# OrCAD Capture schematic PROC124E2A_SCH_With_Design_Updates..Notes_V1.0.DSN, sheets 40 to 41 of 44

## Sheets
40 38. AUDIO CODEC: size C; title: AUDIO CODEC
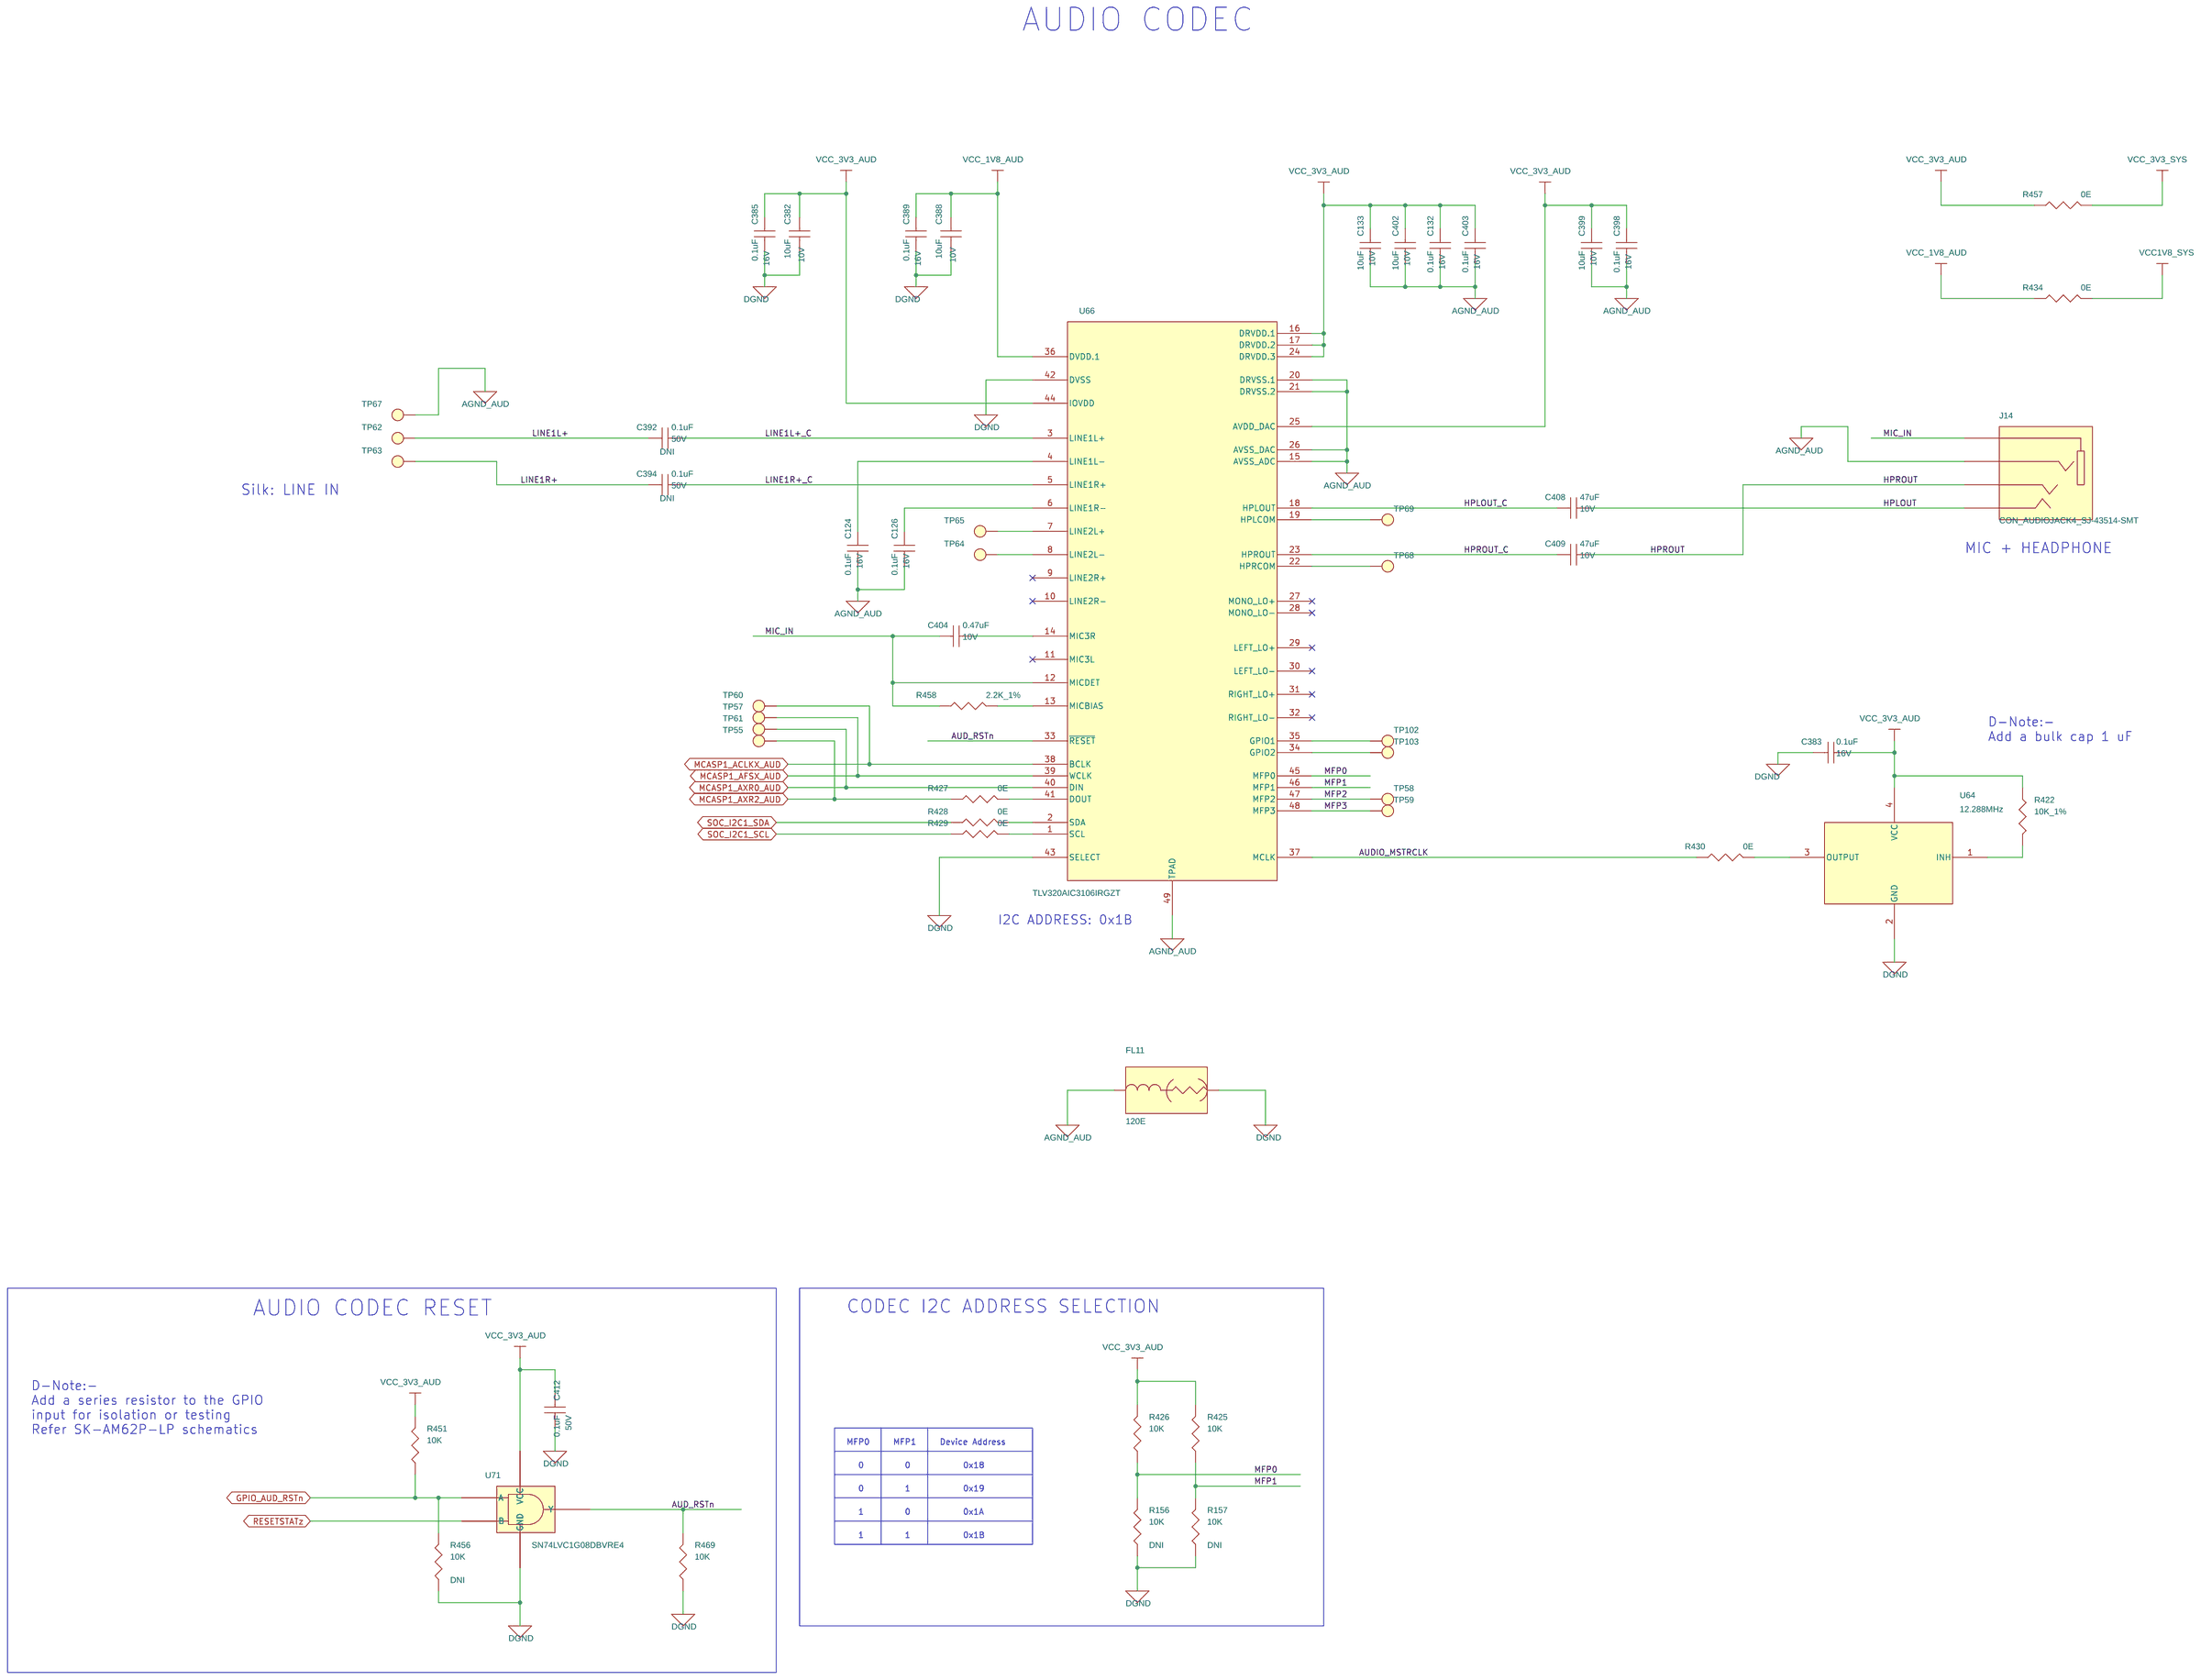
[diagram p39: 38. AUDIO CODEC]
41 40. HDMI INTERFACE: size C; title: HDMI INTERFACE
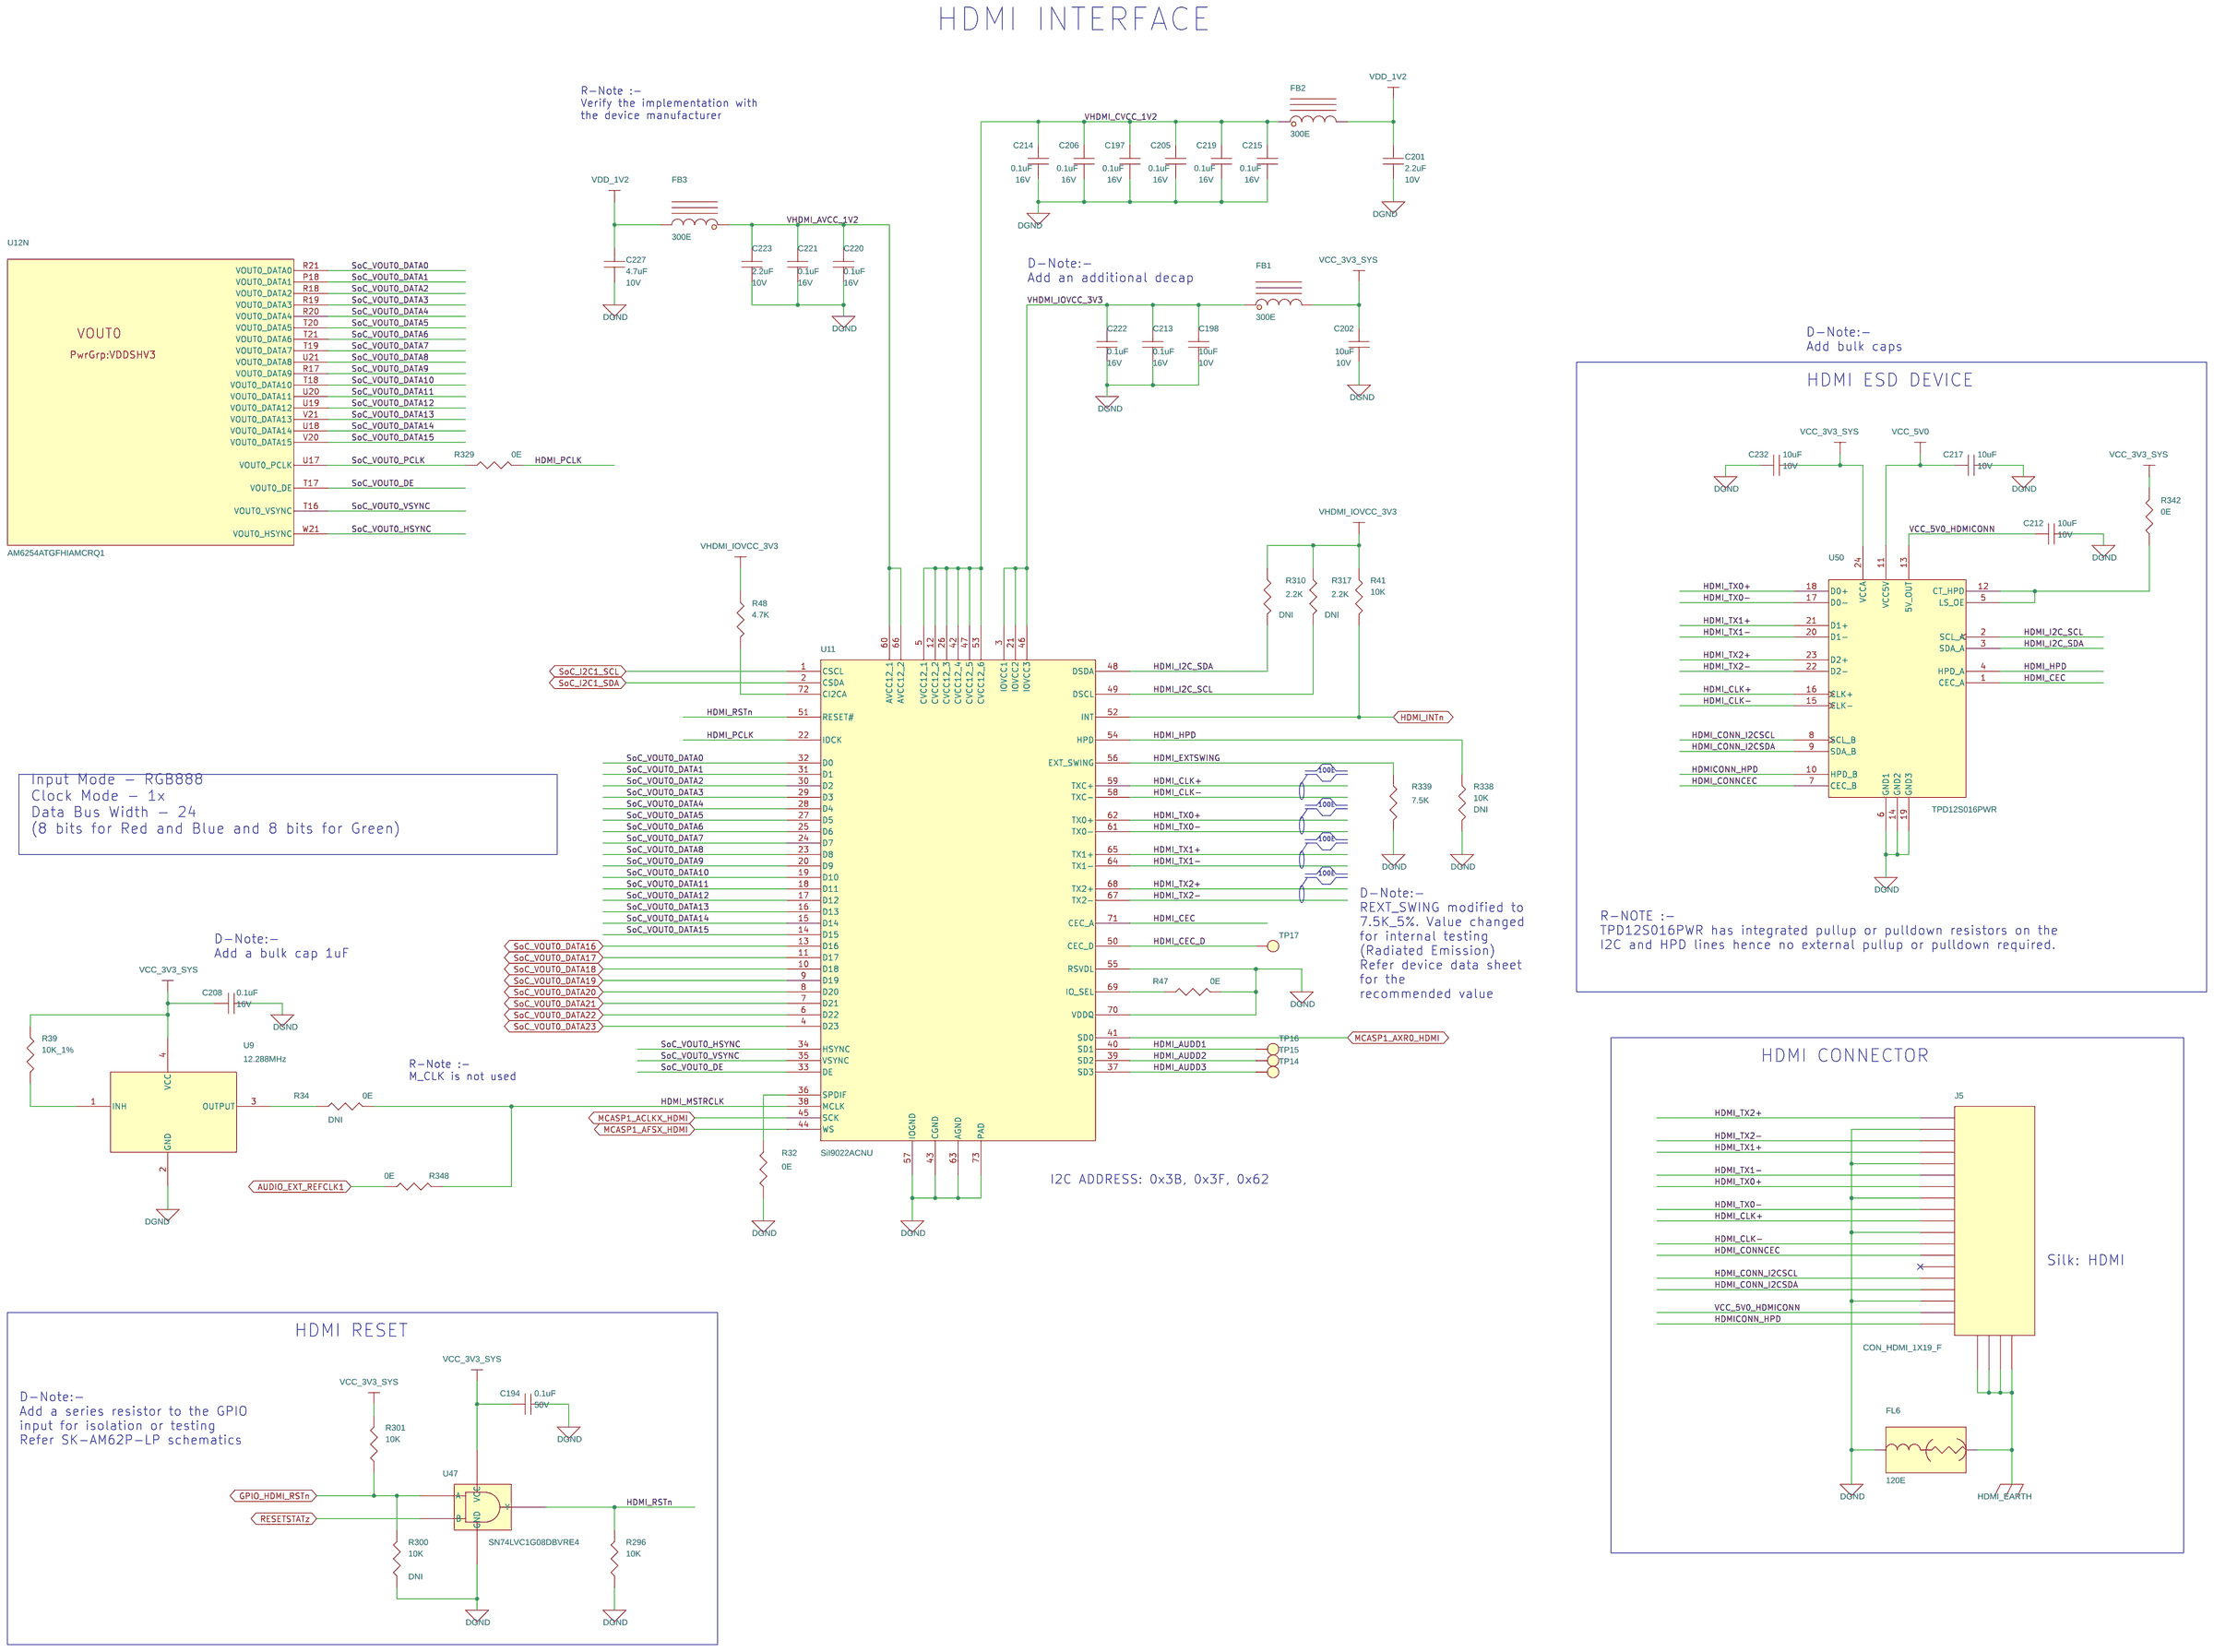
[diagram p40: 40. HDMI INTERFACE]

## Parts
sheet 15. SOC POWER CAPS
U12  AM6254ATGFHIAMCRQ1  [FCBGA441_31-49_680X680_2-6]  (sections A,B,C,D,E,F,G,H,I,J,K,L,M,N,O,P,Q,R)
sheet 38. AUDIO CODEC
C124  0.1uF  [CAP0201_0-5]
C126  0.1uF  [CAP0201_0-5]
C132  0.1uF  [CAP0201_0-5]
C133  10uF  [CAP0402_0-75]
C382  10uF  [CAP0402_0-75]
C383  0.1uF  [CAP0201_0-5]
C385  0.1uF  [CAP0201_0-5]
C388  10uF  [CAP0402_0-75]
C389  0.1uF  [CAP0201_0-5]
C392  0.1uF  [CAP0402_0-75]
C394  0.1uF  [CAP0402_0-75]
C398  0.1uF  [CAP0201_0-5]
C399  10uF  [CAP0402_0-75]
C402  10uF  [CAP0402_0-75]
C403  0.1uF  [CAP0201_0-5]
C404  0.47uF  [CAP0402_0-75]
C408  47uF  [CAP1206_2]
C409  47uF  [CAP1206_2]
C412  0.1uF  [CAP0402_0-75]
FL11  120E  [EMIFIL_BLM15A_0402_0-6]
J14  CON_AUDIOJACK4_SJ-43514-SMT  [CON_AV4_SJ-43514-SMT_S_R_S_5-1]
R156  10K  [RES0201_0-5]
R157  10K  [RES0201_0-5]
R422  10K_1%  [RES0201_0-5]
R425  10K  [RES0201_0-5]
R426  10K  [RES0201_0-5]
R427  0E  [RES0201_0-5]
R428  0E  [RES0201_0-5]
R429  0E  [RES0201_0-5]
R430  0E  [RES0201_0-5]
R434  0E  [RES0402_0-5]
R451  10K  [RES0201_0-5]
R456  10K  [RES0201_0-5]
R457  0E  [RES0402_0-5]
R458  2.2K_1%  [RES0201_0-5]
R469  10K  [RES0201_0-5]
TP55  TP20_SMD  [TP20_SMD]
TP57  TP20_SMD  [TP20_SMD]
TP58  TP20_SMD  [TP20_SMD]
TP59  TP20_SMD  [TP20_SMD]
TP60  TP20_SMD  [TP20_SMD]
TP61  TP20_SMD  [TP20_SMD]
TP62  THRU HOLE  [TP_40X65]
TP63  THRU HOLE  [TP_40X65]
TP64  TP20_SMD  [TP20_SMD]
TP65  TP20_SMD  [TP20_SMD]
TP67  THRU HOLE  [TP_40X65]
TP68  TP20_SMD  [TP20_SMD]
TP69  TP20_SMD  [TP20_SMD]
TP102  TP20_SMD  [TP20_SMD]
TP103  TP20_SMD  [TP20_SMD]
U64  12.288MHz  [OSC4_KC3225Z_130X100_SMD_0-8]
U66  TLV320AIC3106IRGZT  [VQFN48_19-68_285X285]
U71  SN74LVC1G08DBVRE4  [SOT23-5]
sheet 40. HDMI INTERFACE
C194  0.1uF  [CAP0402_0-75]
C197  0.1uF  [CAP0201_0-5]
C198  10uF  [CAP0402_0-75]
C201  2.2uF  [CAP0201_0-5]
C202  10uF  [CAP0402_0-75]
C205  0.1uF  [CAP0201_0-5]
C206  0.1uF  [CAP0201_0-5]
C208  0.1uF  [CAP0201_0-5]
C212  10uF  [CAP0402_0-75]
C213  0.1uF  [CAP0201_0-5]
C214  0.1uF  [CAP0201_0-5]
C215  0.1uF  [CAP0201_0-5]
C217  10uF  [CAP0402_0-75]
C219  0.1uF  [CAP0201_0-5]
C220  0.1uF  [CAP0201_0-5]
C221  0.1uF  [CAP0201_0-5]
C222  0.1uF  [CAP0201_0-5]
C223  2.2uF  [CAP0201_0-5]
C227  4.7uF  [CAP0402_0-75]
C232  10uF  [CAP0402_0-75]
FB1  300E  [IND0603]
FB2  300E  [IND0603]
FB3  300E  [IND0603]
FL6  120E  [EMIFIL_BLM15A_0402_0-6]
J5  CON_HDMI_1X19_F  [CON_19X1_10029449-001RLF_S_R_S_6-3]
R32  0E  [RES0201_0-5]
R34  0E  [RES0201_0-5]
R39  10K_1%  [RES0201_0-5]
R41  10K  [RES0201_0-5]
R47  0E  [RES0201_0-5]
R48  4.7K  [RES0201_0-5]
R296  10K  [RES0201_0-5]
R300  10K  [RES0201_0-5]
R301  10K  [RES0201_0-5]
R310  2.2K  [RES0402_0-5]
R317  2.2K  [RES0402_0-5]
R329  0E  [RES0201_0-5]
R338  10K  [RES0201_0-5]
R339  7.5K  [RES0402_0-5]
R342  0E  [RES0201_0-5]
R348  0E  [RES0201_0-5]
TP14  TP20_SMD  [TP20_SMD]
TP15  TP20_SMD  [TP20_SMD]
TP16  TP20_SMD  [TP20_SMD]
TP17  TP20_SMD  [TP20_SMD]
U9  12.288MHz  [OSC4_KC3225Z_130X100_SMD_0-8]
U11  SiI9022ACNU  [QFN72_19-68_390X390_0-9]
U47  SN74LVC1G08DBVRE4  [SOT23-5]
U50  TPD12S016PWR  [TSSOP24_25-59_315X180_1-2]

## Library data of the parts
U12 = AM6254ATGFHIAMCRQ1_FCBGA441: IC AM62Q SoC MICROPROCESSOR FCBGA441; Chkd/date: PRADEEP/180324; Crtd /date: TAMILARASU/180324; Custom_Duty: 15%; Customs_HS_Code: 85423100; Distributor_name: NA; Distributor_part_number: NA; Footprint Path: Y:\MIS_DATABASE\Library\ALTIUM_TOOL\PCB_FOOTPRINTS\Altium_Footprint_Lib.PcbLib; Height: 2.57MM; Library Path: Y:\MIS_DATABASE\Library\ALTIUM_TOOL\SCHEMATICS_PARTS\MS_MICROPROCESSOR_Library.schlib; Mfr_name: TEXAS INSTRUMENTS; Mistral Part No: 141224030001-R; Package: FCBGA441; Part_type: ICS\DIGITAL\MICROPROCESSOR; Project: TI_AM62Q_BRD; RoHS: NA; Temperature: NA; Tolerance: NA; Voltage: NA; Wattage: NA; Weight: NA; Datasheet: Y:\MIS_DATABASE\DATASHEETS\ICS\DIGITAL\MICROCONTROLLER\AM62Q-SoC.PDF
C124 C126 C132 C197 C205 C206 C213-C215 C219-C222 C383 C385 C389 C398 C403 = CAP: CAP CERAMIC 0.1uF 16V 10% X5R 0201; Chkd/date: MANIRAJA/230118; Crtd /date: MANIRAJA/230118; Custom_Duty: 15%; Customs_HS_Code: 85322990; Distributor_name: DIGIKEY; Distributor_part_number: 490-14305-1-ND; Footprint Path: Y:\MIS_DATABASE\Library\ALTIUM_TOOL\PCB_FOOTPRINTS\Altium_Footprint_Lib.PcbLib; Height: 0.33MM; Library Path: Y:\MIS_DATABASE\Library\ALTIUM_TOOL\SCHEMATICS_PARTS\MS_DISCRETE_Library.schlib; Mfr_name: MURATA; Mfr_part_number: GRM033R61C104KE14D; Mistral Part No: 120009030072-R; Package: 0201; Part_type: CAPACITORS\CERAMIC; Project: TI_MAXIE_CPB; RoHS: RoHS; Temperature: -55°C+85°C; Tolerance: 10%; Voltage: 16V; Wattage: NA; Weight: 0.33mg; Datasheet: Y:\MIS_DATABASE\DATASHEETS\CAPACITORS\GRM033R61C104KE14.PDF
C133 C198 C202 C212 C217 C232 C382 C388 C399 C402 = CAP: CAP CERAMIC 10uF 10V 20% X5R 0402; Chkd/date: MANIRAJA/300520; Crtd /date: ALVY/260520; Custom_Duty: 15%; Customs_HS_Code: 85322990; Distributor_name: DIGIKEY; Distributor_part_number: 490-GRM155R61A106ME11DTR-ND; Footprint Path: Y:\MIS_DATABASE\Library\ALTIUM_TOOL\PCB_FOOTPRINTS\Altium_Footprint_Lib.PcbLib; Height: 0.55MM; Library Path: Y:\MIS_DATABASE\Library\ALTIUM_TOOL\SCHEMATICS_PARTS\MS_DISCRETE_Library.schlib; Mfr_name: MURATA; Mfr_part_number: GRM155R61A106ME11D; Mistral Part No: 120013110019-R; Package: 0402; Part_type: CAPACITORS\CERAMIC; Project: QCS610_NANOSOM; RoHS: RoHS; Temperature: -55°C+85°C; Tolerance: 20%; Voltage: 10V; Wattage: NA; Weight: 3.1mg; Datasheet: Y:\MIS_DATABASE\DATASHEETS\CAPACITORS\MURATA-GXX-SER_NOV17.PDF
C392 C394 = CAP: CAP CERAMIC 0.1uF 50V 10% X7R 0402; Assembly_Instruction: DNI; Chkd/date: MANIRAJA/261020; Crtd /date: ALVY/211020; Custom_Duty: 15%; Customs_HS_Code: 85322990; Distributor_name: DIGIKEY; Distributor_part_number: 490-10700-1-ND; Footprint Path: Y:\MIS_DATABASE\Library\ALTIUM_TOOL\PCB_FOOTPRINTS\Altium_Footprint_Lib.PcbLib; Height: 0.55MM; Library Path: Y:\MIS_DATABASE\Library\ALTIUM_TOOL\SCHEMATICS_PARTS\MS_DISCRETE_Library.schlib; Mfr_name: MURATA; Mfr_part_number: GRM155R71H104KE14D; Mistral Part No: 120011100014-R; Package: 0402; Part_type: CAPACITORS\CERAMIC; Project: J7_CP; RoHS: RoHS; Temperature: -55°C+125°C; Tolerance: 10%; Voltage: 50V; Wattage: NA; Weight: 3.1mg; Datasheet: Y:\MIS_DATABASE\DATASHEETS\CAPACITORS\GRM155R71H104KE14.PDF
C404 = CAP: CAP CERAMIC 0.47uF 10V 10% X7R 0402; Chkd/date: MANIRAJA/310821; Crtd /date: ALVY/310821; Custom_Duty: 15%; Customs_HS_Code: 85322990; Distributor_name: DIGIKEY; Distributor_part_number: 490-14366-1-ND; Footprint Path: Y:\MIS_DATABASE\Library\ALTIUM_TOOL\PCB_FOOTPRINTS\Altium_Footprint_Lib.PcbLib; Height: 0.55MM; Library Path: Y:\MIS_DATABASE\Library\ALTIUM_TOOL\SCHEMATICS_PARTS\MS_DISCRETE_Library.schlib; Mfr_name: MURATA; Mfr_part_number: GRM155R71A474KE01D; Mistral Part No: 120021060019-R; Package: 0402; Part_type: CAPACITORS\CERAMIC; Project: TI_AM335x SK_BRD; RoHS: RoHS; Temperature: -55°C+125°C; Tolerance: 10%; Voltage: 10V; Wattage: NA; Weight: 1.5mg; Datasheet: Y:\MIS_DATABASE\DATASHEETS\CAPACITORS\GRM155R71A474KE01.PDF
C408 C409 = CAP: CAP CERAMIC 47uF 10V 20% X5R 1206; Chkd/date: USMAN/121213; Crtd /date: USMAN/121213; Custom_Duty: 15%; Customs_HS_Code: 85322990; Distributor_name: DIGIKEY; Distributor_part_number: 490-5528-1-ND; Footprint Path: Y:\MIS_DATABASE\Library\ALTIUM_TOOL\PCB_FOOTPRINTS\Altium_Footprint_Lib.PcbLib; Height: 1.80MM; Library Path: Y:\MIS_DATABASE\Library\ALTIUM_TOOL\SCHEMATICS_PARTS\MS_DISCRETE_Library.schlib; Mfr_name: MURATA; Mfr_part_number: GRM31CR61A476ME15L; Mistral Part No: 120013120015-R; Package: 1206; Part_type: CAPACITORS\CERAMIC; Project: DMP; RoHS: RoHS; Temperature: -55°C+85°C; Tolerance: 20%; Voltage: 10V; Wattage: NA; Weight: 40mg; Datasheet: Y:\MIS_DATABASE\DATASHEETS\CAPACITORS\MURATA-GXX-SER_NOV17.PDF
C412 = CAP: CAP CERAMIC 0.1uF 50V 10% X7R 0402; Chkd/date: MANIRAJA/261020; Crtd /date: ALVY/211020; Custom_Duty: 15%; Customs_HS_Code: 85322990; Distributor_name: DIGIKEY; Distributor_part_number: 490-10700-1-ND; Footprint Path: Y:\MIS_DATABASE\Library\ALTIUM_TOOL\PCB_FOOTPRINTS\Altium_Footprint_Lib.PcbLib; Height: 0.55MM; Library Path: Y:\MIS_DATABASE\Library\ALTIUM_TOOL\SCHEMATICS_PARTS\MS_DISCRETE_Library.schlib; Mfr_name: MURATA; Mfr_part_number: GRM155R71H104KE14D; Mistral Part No: 120011100014-R; Package: 0402; Part_type: CAPACITORS\CERAMIC; Project: J7_CP; RoHS: RoHS; Temperature: -55°C+125°C; Tolerance: 10%; Voltage: 50V; Wattage: NA; Weight: 3.1mg; Datasheet: Y:\MIS_DATABASE\DATASHEETS\CAPACITORS\GRM155R71H104KE14.PDF
FL6 FL11 = EMIFILTER_IND: IND FERRITE BEAD CHIP 120E 2A 0402; Chkd/date: NAVEED/241114; Crtd /date: USMAN/170613; Custom_Duty: 24%; Customs_HS_Code: 85369090; Distributor_name: DIGIKEY; Distributor_part_number: 490-9656-1-ND; Footprint Path: Y:\MIS_DATABASE\Library\ALTIUM_TOOL\PCB_FOOTPRINTS\Altium_Footprint_Lib.PcbLib; Height: 0.55MM; Library Path: Y:\MIS_DATABASE\Library\ALTIUM_TOOL\SCHEMATICS_PARTS\MS_FILTER_Library.schlib; Mfr_name: MURATA; Mfr_part_number: BLM15PX121SN1D; Mistral Part No: 130013060022-R; Package: 0402; Part_type: INDUCTOR; Project: GEN_3-8; RoHS: RoHS; Temperature: -55°C+125°C; Tolerance: 25%; Voltage: NA; Wattage: NA; Weight: 1mg; Datasheet: Y:\MIS_DATABASE\DATASHEETS\DISCRETES\INDUCTORS\BLM15-SN1-SER.PDF
J14 = CON_AUDIOJACK4_SJ-43514-SMT: CON AUDIO JACK 4POS FEMALE RT SMD; Chkd/date: MAZHAR/230211; Crtd /date: MUDDU/300610; Custom_Duty: 24%; Customs_HS_Code: 85369090; Distributor_name: DIGIKEY; Distributor_part_number: CP-43514SJCT-ND; Footprint Path: Y:\MIS_DATABASE\Library\ALTIUM_TOOL\PCB_FOOTPRINTS\Altium_Footprint_Lib.PcbLib; Height: 5.10MM; Library Path: Y:\MIS_DATABASE\Library\ALTIUM_TOOL\SCHEMATICS_PARTS\MS_CONNECTOR_Library.schlib; Mfr_name: CUI INC; Mfr_part_number: SJ-43514-SMT-TR; Mistral Part No: 150010060028-R; Package: SMD; Part_type: CONNECTOR\JACK; Project: PB_BUGBASE; RoHS: RoHS; Temperature: -25°C+85°C; Tolerance: NA; Voltage: NA; Wattage: NA; Weight: 1100mg; Datasheet: Y:\MIS_DATABASE\DATASHEETS\CONNECTORS\SJ-4351X-SMT.PDF
R156 R157 R300 R338 R456 = RESISTOR: RES 10K 1/20W 5% 0201; Assembly_Instruction: DNI; Chkd/date: MANIRAJA/050517; Crtd /date: MANIRAJA/050517; Custom_Duty: 15%; Customs_HS_Code: 85332119; Distributor_name: DIGIKEY; Distributor_part_number: 311-10KNCT-ND; Footprint Path: Y:\MIS_DATABASE\Library\ALTIUM_TOOL\PCB_FOOTPRINTS\Altium_Footprint_Lib.PcbLib; Height: 0.26MM; Library Path: Y:\MIS_DATABASE\Library\ALTIUM_TOOL\SCHEMATICS_PARTS\MS_DISCRETE_Library.schlib; Mfr_name: YAGEO AMERICA; Mfr_part_number: RC0201JR-0710KL; Mistral Part No: 110010070051-R; Package: 0201; Part_type: RESISTORS\FIXED; Project: GOLDEN-I LITE; RoHS: RoHS; Temperature: -55°C+125°C; Tolerance: 5%; Voltage: NA; Wattage: 1/20W; Weight: 0.17mg; Datasheet: Y:\MIS_DATABASE\DATASHEETS\RESISTORS\RCXXXXL-SER_MAR18.PDF
R39 R422 = RESISTOR: RES 10K 1/20W 1% 0201; Chkd/date: VASANTHA/270117; Crtd /date: MANIRAJA/270117; Custom_Duty: 15%; Customs_HS_Code: 85332119; Distributor_name: DIGIKEY; Distributor_part_number: 311-10.0KMCT-ND; Footprint Path: Y:\MIS_DATABASE\Library\ALTIUM_TOOL\PCB_FOOTPRINTS\Altium_Footprint_Lib.PcbLib; Height: 0.26MM; Library Path: Y:\MIS_DATABASE\Library\ALTIUM_TOOL\SCHEMATICS_PARTS\MS_DISCRETE_Library.schlib; Mfr_name: YAGEO AMERICA; Mfr_part_number: RC0201FR-0710KL; Mistral Part No: 110011040018-R; Package: 0201; Part_type: RESISTORS\FIXED; Project: GOLDEN-I LITE; RoHS: RoHS; Temperature: -55°C+125°C; Tolerance: 1%; Voltage: NA; Wattage: 1/20W; Weight: 0.17mg; Datasheet: Y:\MIS_DATABASE\DATASHEETS\RESISTORS\RCXXXXL-SER_MAR18.PDF
R41 R296 R301 R425 R426 R451 R469 = RESISTOR: RES 10K 1/20W 5% 0201; Chkd/date: MANIRAJA/050517; Crtd /date: MANIRAJA/050517; Custom_Duty: 15%; Customs_HS_Code: 85332119; Distributor_name: DIGIKEY; Distributor_part_number: 311-10KNCT-ND; Footprint Path: Y:\MIS_DATABASE\Library\ALTIUM_TOOL\PCB_FOOTPRINTS\Altium_Footprint_Lib.PcbLib; Height: 0.26MM; Library Path: Y:\MIS_DATABASE\Library\ALTIUM_TOOL\SCHEMATICS_PARTS\MS_DISCRETE_Library.schlib; Mfr_name: YAGEO AMERICA; Mfr_part_number: RC0201JR-0710KL; Mistral Part No: 110010070051-R; Package: 0201; Part_type: RESISTORS\FIXED; Project: GOLDEN-I LITE; RoHS: RoHS; Temperature: -55°C+125°C; Tolerance: 5%; Voltage: NA; Wattage: 1/20W; Weight: 0.17mg; Datasheet: Y:\MIS_DATABASE\DATASHEETS\RESISTORS\RCXXXXL-SER_MAR18.PDF
R32 R47 R342 R348 R427-R430 = RESISTOR: RES 0E 1/20W 5% 0201; Chkd/date: NAVEED/301214; Crtd /date: MUDDU/120710; Custom_Duty: 15%; Customs_HS_Code: 85332119; Distributor_name: DIGIKEY; Distributor_part_number: 311-0.0NCT-ND; Footprint Path: Y:\MIS_DATABASE\Library\ALTIUM_TOOL\PCB_FOOTPRINTS\Altium_Footprint_Lib.PcbLib; Height: 0.26MM; Library Path: Y:\MIS_DATABASE\Library\ALTIUM_TOOL\SCHEMATICS_PARTS\MS_DISCRETE_Library.schlib; Mfr_name: YAGEO AMERICA; Mfr_part_number: RC0201JR-070RL; Mistral Part No: 110010070067-R; Package: 0201; Part_type: RESISTORS\FIXED; Project: PB_BUGBASE; RoHS: RoHS; Temperature: -55°C+125°C; Tolerance: 5%; Voltage: NA; Wattage: 1/20W; Weight: 0.17mg; Datasheet: Y:\MIS_DATABASE\DATASHEETS\RESISTORS\RCXXXXL-SER_MAR18.PDF
R434 R457 = RESISTOR: RES 0E 1/16W JUMPER 0402; Chkd/date: VASANTHA/201216; Crtd /date: MUDDU/190810; Custom_Duty: 15%; Customs_HS_Code: 85332119; Distributor_name: DIGIKEY; Distributor_part_number: 541-0.0JCT-ND; Footprint Path: Y:\MIS_DATABASE\Library\ALTIUM_TOOL\PCB_FOOTPRINTS\Altium_Footprint_Lib.PcbLib; Height: 0.40MM; Library Path: Y:\MIS_DATABASE\Library\ALTIUM_TOOL\SCHEMATICS_PARTS\MS_DISCRETE_Library.schlib; Mfr_name: VISHAY; Mfr_part_number: CRCW04020000Z0ED; Mistral Part No: 110010080019-R; Package: 0402; Part_type: RESISTORS\FIXED; Project: PB_BUGBASE; RoHS: RoHS; Temperature: -55°C+155°C; Tolerance: NA; Voltage: NA; Wattage: 1/16W; Weight: 0.65mg; Datasheet: Y:\MIS_DATABASE\DATASHEETS\RESISTORS\CRCW0603.PDF
R458 = RESISTOR: RES 2.2K 1/20W 1% 0201; Chkd/date: VASANTHA/270117; Crtd /date: MANIRAJA/270117; Custom_Duty: 15%; Customs_HS_Code: 85332119; Distributor_name: DIGIKEY; Distributor_part_number: YAG2572CT-ND; Footprint Path: Y:\MIS_DATABASE\Library\ALTIUM_TOOL\PCB_FOOTPRINTS\Altium_Footprint_Lib.PcbLib; Height: 0.26MM; Library Path: Y:\MIS_DATABASE\Library\ALTIUM_TOOL\SCHEMATICS_PARTS\MS_DISCRETE_Library.schlib; Mfr_name: YAGEO AMERICA; Mfr_part_number: RC0201FR-072K2L; Mistral Part No: 110017010016-R; Package: 0201; Part_type: RESISTORS\FIXED; Project: GOLDEN-I LITE; RoHS: RoHS; Temperature: -55°C+125°C; Tolerance: 1%; Voltage: NA; Wattage: 1/20W; Weight: 0.17mg; Datasheet: Y:\MIS_DATABASE\DATASHEETS\RESISTORS\RCXXXXL-SER_MAR18.PDF
TP14-TP17 TP55 TP57-TP61 TP64 TP65 TP68 TP69 TP102 TP103 = TESTPOINT: TESTPOINT CIR 20 SMD; Chkd/date: SHREESHAIL/171006; Crtd /date: MAZHAR/171006; Custom_Duty: NA; Customs_HS_Code: NA; Distributor_name: NA; Distributor_part_number: NA; Footprint Path: Y:\MIS_DATABASE\Library\ALTIUM_TOOL\PCB_FOOTPRINTS\Altium_Footprint_Lib.PcbLib; Height: NA; Library Path: Y:\MIS_DATABASE\Library\ALTIUM_TOOL\SCHEMATICS_PARTS\MS_DISCRETE_Library.schlib; MECHANICAL 3D STEP FILE: NA; Mfr_name: LOCAL; Mistral Part No: NA; Package: SMD; Project: BT MODULE_CSRBC04; RoHS: NA; Temperature: NA; Tolerance: NA; Voltage: NA; Wattage: NA; Weight: NA; Datasheet: NA
TP62 TP63 TP67 = TESTPOINT: TESTPOINT 1.0MM DRILL PTH; Chkd/date: MAZHAR/271211; Crtd /date: SHREESHAIL/041005; Distributor_name: NA; Distributor_part_number: NA; Height: NA; Mfr_name: LOCAL; Mistral Part No: 130009030938; Package: THRU-HOLE; Project: HSE; Datasheet: NA
U9 U64 = OSC_KC2016K: OSC 12.288MHz CMOS SMD; Chkd/date: ALVY/240322; Crtd /date: ALVY/240322; Custom_Duty: 24%; Customs_HS_Code: 85437099; Distributor_name: DIGIKEY; Distributor_part_number: 478-KC3225Z12.2880C1KX00CT-ND; Footprint Path: Y:\MIS_DATABASE\Library\ALTIUM_TOOL\PCB_FOOTPRINTS\Altium_Footprint_Lib.PcbLib; Height: 0.80MM; Library Path: Y:\MIS_DATABASE\Library\ALTIUM_TOOL\SCHEMATICS_PARTS\MS_DISCRETE_Library.schlib; Mfr_name: KYOCERA; Mfr_part_number: KC3225Z12.2880C1KX00; Mistral Part No: 130022030052-R; Package: SMD; Part_type: OSCILLATORS; Project: TI_SK-AM62Q-LP EVM_BRD; RoHS: RoHS; Temperature: -40°C+85°C; Tolerance: NA; Voltage: NA; Wattage: NA; Weight: NA; Datasheet: Y:\MIS_DATABASE\DATASHEETS\MISC\CRY_OSC\KC-Z-SERPDF
U66 = TLV320AIC3106IRGZT_VQFN48: IC LOW-POWER STEREO AUDIO CODEC VQFN48; Chkd/date: SUHAS/261010; Crtd /date: MUDDU/150610; Custom_Duty: 15%; Customs_HS_Code: 85423100; Distributor_name: DIGIKEY; Distributor_part_number: TLV320AIC3106IRGZT-ND; Height: 1.00MM; Mfr_name: TEXAS INSTRUMENTS; Mistral Part No: 143010060003-R; Package: VQFN48; Part_type: ICS\TELECOM\CODEC; Project: CENTAURUS; RoHS: Sb/ Br FREE; Temperature: -40°C+85°C; Weight: NA; Datasheet: Y:\MIS_DATABASE\DATASHEETS\ICS\TELECOM\TLV320AIC3106IRGZT.PDF
U47 U71 = SN74LVC1G08DBVRE4_SOT23-5: IC SINGLE 2-INPUT POSITIVE AND GATE SOT23-5; Chkd/date: SUHAS/221010; Crtd /date: USMAN/151008; Custom_Duty: 15%; Customs_HS_Code: 85423100; Distributor_name: DIGIKEY; Distributor_part_number: SN74LVC1G08DBVRE4-ND; Height: 1.45MM; Mfr_name: TEXAS INSTRUMENTS; Mistral Part No: 141009060026-R; Part_type: ICS\DIGITAL\GATES; Project: KHAN_MAIN; RoHS: Sb/ Br FREE; Temperature: -40°C+85°C; Datasheet: Y:\MIS_DATABASE\DATASHEETS\ICS\DIGITAL\GATES\SN74LVC1G08.PDF
C194 = CAP: CAP CERAMIC 0.1uF 50V 10% X7R 0402; Alt_Mfr_name: YAGEO AMERICA; Alt_Mfr_part_number: CC0402KRX5R8BB104; Chkd/date: MANIRAJA/261020; Crtd /date: ALVY/211020; Custom_Duty: 15%; Customs_HS_Code: 85322990; Distributor_name: DIGIKEY; Distributor_part_number: 490-10700-1-ND; Footprint Path: Y:\MIS_DATABASE\Library\ALTIUM_TOOL\PCB_FOOTPRINTS\Altium_Footprint_Lib.PcbLib; Height: 0.55MM; Library Path: Y:\MIS_DATABASE\Library\ALTIUM_TOOL\SCHEMATICS_PARTS\MS_DISCRETE_Library.schlib; Mfr_name: MURATA; Mfr_part_number: GRM155R71H104KE14D; Mistral Part No: 120011100014-R; Package: 0402; Part_type: CAPACITORS\CERAMIC; Project: J7_CP; RoHS: RoHS; Temperature: -55°C+125°C; Tolerance: 10%; Voltage: 50V; Wattage: NA; Weight: 3.1mg; Datasheet: Y:\MIS_DATABASE\DATASHEETS\CAPACITORS\GRM155R71H104KE14.PDF
C201 C223 = CAP: CAP CERAMIC 2.2uF 10V 10% X5R 0201; Chkd/date: MANIRAJA/220918; Crtd /date: MANIRAJA/220918; Custom_Duty: 15%; Customs_HS_Code: 85322990; Distributor_name: DIGIKEY; Distributor_part_number: 490-13227-1-ND; Footprint Path: Y:\MIS_DATABASE\Library\ALTIUM_TOOL\PCB_FOOTPRINTS\Altium_Footprint_Lib.PcbLib; Height: 0.39MM; Library Path: Y:\MIS_DATABASE\Library\ALTIUM_TOOL\SCHEMATICS_PARTS\MS_DISCRETE_Library.schlib; Mfr_name: MURATA; Mfr_part_number: GRM033R61A225KE47D; Mistral Part No: 120018090044-R; Package: 0201; Part_type: CAPACITORS\CERAMIC; Project: TI_60GHz-AOP; RoHS: RoHS; Temperature: -55°C+85°C; Tolerance: 10%; Voltage: 10V; Wattage: NA; Weight: 0.33mg; Datasheet: Y:\MIS_DATABASE\DATASHEETS\CAPACITORS\GRM033R61A225KE47D.PDF
C208 = CAP: CAP CERAMIC 0.1uF 16V 10% X5R 0201; Alt_Mfr_name: YAGEO AMERICA; Alt_Mfr_part_number: CC0402KRX5R8BB104; Chkd/date: MANIRAJA/230118; Crtd /date: MANIRAJA/230118; Custom_Duty: 15%; Customs_HS_Code: 85322990; Distributor_name: DIGIKEY; Distributor_part_number: 490-14305-1-ND; Footprint Path: Y:\MIS_DATABASE\Library\ALTIUM_TOOL\PCB_FOOTPRINTS\Altium_Footprint_Lib.PcbLib; Height: 0.33MM; Library Path: Y:\MIS_DATABASE\Library\ALTIUM_TOOL\SCHEMATICS_PARTS\MS_DISCRETE_Library.schlib; Mfr_name: MURATA; Mfr_part_number: GRM033R61C104KE14D; Mistral Part No: 120009030072-R; Package: 0201; Part_type: CAPACITORS\CERAMIC; Project: TI_MAXIE_CPB; RoHS: RoHS; Temperature: -55°C+85°C; Tolerance: 10%; Voltage: 16V; Wattage: NA; Weight: 0.33mg; Datasheet: Y:\MIS_DATABASE\DATASHEETS\CAPACITORS\GRM033R61C104KE14.PDF
C227 = CAP: CAP CERAMIC 4.7uF 10V 20% X5R 0402; Chkd/date: MANIRAJA/110718; Crtd /date: ALVY/110718; Custom_Duty: 15%; Customs_HS_Code: 85322990; Distributor_name: DIGIKEY; Distributor_part_number: 490-14306-1-ND; Footprint Path: Y:\MIS_DATABASE\Library\ALTIUM_TOOL\PCB_FOOTPRINTS\Altium_Footprint_Lib.PcbLib; Height: 0.65MM; Library Path: Y:\MIS_DATABASE\Library\ALTIUM_TOOL\SCHEMATICS_PARTS\MS_DISCRETE_Library.schlib; Mfr_name: MURATA; Mfr_part_number: GRM155R61A475MEAAD; Mistral Part No: 120012060002-R; Package: 0402; Part_type: CAPACITORS\CERAMIC; Project: TI_J7SVB_PCIE_ADD-ON-CARD; RoHS: RoHS; Temperature: -55°C+85°C; Tolerance: 20%; Voltage: 10V; Wattage: NA; Weight: 14mg; Datasheet: Y:\MIS_DATABASE\DATASHEETS\CAPACITORS\GRM155R61A475MEAAD.PDF
FB1-FB3 = INDUCTOR_FERRITE: IND FERRITE CHIP 300E 500mA 0603; Alternate_mfr_name_A: TDK CORPORATION; Alternate_mfr_part_number_A: MMZ1608R301ATA00; Chkd/date: VASANTHA/190614; Crtd /date: NAVEED/160614; Custom_Duty: 24%; Customs_HS_Code: 85437099; Distributor_name: DIGIKEY; Distributor_name_A: DIGIKEY; Distributor_part_number: 445-2171-1-ND; Distributor_part_number_A: 445-2171-1-ND; Height: 0.75MM; Mfr_name: TDK CORPORATION; Mfr_part_number: MMZ1608R301A; Mistral Part No: 130014060028-R; Package: 0603; Part_type: INDUCTOR; Project: AEGIS_POM; RoHS: RoHS; Temperature: -55°C+125°C; Tolerance: NA; Voltage: NA; Wattage: NA; Weight: NA; Datasheet: Y:\MIS_DATABASE\DATASHEETS\DISCRETES\INDUCTORS\MMZSER.PDF
J5 = CON_HDMI_19X1: CON HDMI-A TYPE 1X19 0.50MM PITCH FEMALE RT SMD; Chkd/date: VASANTHA/060117; Crtd /date: MUDDU/060510; Custom_Duty: 24%; Customs_HS_Code: 85369090; Distributor_name: DIGIKEY; Distributor_part_number: 609-1010-1-ND; Footprint Path: Y:\MIS_DATABASE\Library\ALTIUM_TOOL\PCB_FOOTPRINTS\Altium_Footprint_Lib.PcbLib; Height: 6.30MM; Library Path: Y:\MIS_DATABASE\Library\ALTIUM_TOOL\SCHEMATICS_PARTS\MS_CONNECTOR_Library.schlib; Mfr_name: FCI; Mfr_part_number: 10029449-001RLF; Mistral Part No: 150010050001-R; Package: SMD; Part_type: CONNECTOR\HDMI; Project: SHIVA; RoHS: RoHS; Temperature: -20°C+85°C; Tolerance: NA; Voltage: NA; Wattage: NA; Weight: 2700mg; Datasheet: Y:\MIS_DATABASE\DATASHEETS\CONNECTORS\10029449-001RLF.PDF
R34 = RESISTOR: RES 0E 1/20W 5% 0201; Assembly_Instruction: DNI; Chkd/date: NAVEED/301214; Crtd /date: MUDDU/120710; Custom_Duty: 15%; Customs_HS_Code: 85332119; Distributor_name: DIGIKEY; Distributor_part_number: 311-0.0NCT-ND; Footprint Path: Y:\MIS_DATABASE\Library\ALTIUM_TOOL\PCB_FOOTPRINTS\Altium_Footprint_Lib.PcbLib; Height: 0.26MM; Library Path: Y:\MIS_DATABASE\Library\ALTIUM_TOOL\SCHEMATICS_PARTS\MS_DISCRETE_Library.schlib; Mfr_name: YAGEO AMERICA; Mfr_part_number: RC0201JR-070RL; Mistral Part No: 110010070067-R; Package: 0201; Part_type: RESISTORS\FIXED; Project: PB_BUGBASE; RoHS: RoHS; Temperature: -55°C+125°C; Tolerance: 5%; Voltage: NA; Wattage: 1/20W; Weight: 0.17mg; Datasheet: Y:\MIS_DATABASE\DATASHEETS\RESISTORS\RCXXXXL-SER_MAR18.PDF
R48 = RESISTOR: RES 4.7K 1/20W 5% 0201; Chkd/date: MANIRAJA/200921; Crtd /date: ALVY/200921; Custom_Duty: 15%; Customs_HS_Code: 85332119; Distributor_name: DIGIKEY; Distributor_part_number: 311-4.7KNCT-ND; Footprint Path: Y:\MIS_DATABASE\Library\ALTIUM_TOOL\PCB_FOOTPRINTS\Altium_Footprint_Lib.PcbLib; Height: 0.26MM; Library Path: Y:\MIS_DATABASE\Library\ALTIUM_TOOL\SCHEMATICS_PARTS\MS_DISCRETE_Library.schlib; Mfr_name: YAGEO AMERICA; Mfr_part_number: RC0201JR-074K7L; Mistral Part No: 110021090007-R; Package: 0201; Part_type: RESISTORS\FIXED; Project: TI_AM62x SKEVM_BRD; RoHS: RoHS; Temperature: -55°C+125°C; Tolerance: 5%; Voltage: NA; Wattage: 1/20W; Weight: 0.17mg; Datasheet: Y:\MIS_DATABASE\DATASHEETS\RESISTORS\RCXXXXL-SER_MAR18.PDF
R310 R317 = RESISTOR: RES 2.2K 1/16W 5% 0402; Assembly_Instruction: DNI; Chkd/date: VASANTHA/061216; Crtd /date: BAVISH/021210; Custom_Duty: 15%; Customs_HS_Code: 85332119; Distributor_name: DIGIKEY; Distributor_part_number: 311-2.2KJRCT-ND; Footprint Path: Y:\MIS_DATABASE\Library\ALTIUM_TOOL\PCB_FOOTPRINTS\Altium_Footprint_Lib.PcbLib; Height: 0.40MM; Library Path: Y:\MIS_DATABASE\Library\ALTIUM_TOOL\SCHEMATICS_PARTS\MS_DISCRETE_Library.schlib; Mfr_name: YAGEO AMERICA; Mfr_part_number: RC0402JR-072K2L; Mistral Part No: 110010120018-R; Package: 0402; Part_type: RESISTORS\FIXED; Project: TE4; RoHS: RoHS; Temperature: -55°C+155°C; Tolerance: 5%; Voltage: NA; Wattage: 1/16W; Weight: 0.65mg; Datasheet: Y:\MIS_DATABASE\DATASHEETS\RESISTORS\RCXXXXL-SER_MAR18.PDF
R329 = RESISTOR: RES 0E 1/20W 5% 0201; Chkd/date: NAVEED/301214; Crtd /date: MUDDU/120710; Custom_Duty: 15%; Customs_HS_Code: 85332119; Distributor_name: DIGIKEY; Distributor_part_number: 311-0.0NCT-ND; Footprint Path: Y:\MIS_DATABASE\Library\ALTIUM_TOOL\PCB_FOOTPRINTS\Altium_Footprint_Lib.PcbLib; Height: 0.26MM; Library Path: Y:\MIS_DATABASE\Library\ALTIUM_TOOL\SCHEMATICS_PARTS\MS_DISCRETE_Library.schlib; Mfr_name: YAGEO AMERICA; Mfr_part_number: RC0201JR-070RL; Mistral Part No: 110010070067-R; Package: 0201; Part_type: RESISTORS\FIXED; Project: PB_BUGBASE; RoHS: RoHS; SIGNAL_MODEL: RESISTOR_RES0201_0-5_0E_0E; Temperature: -55°C+125°C; Tolerance: 5%; Voltage: NA; Wattage: 1/20W; Weight: 0.17mg; Datasheet: Y:\MIS_DATABASE\DATASHEETS\RESISTORS\RCXXXXL-SER_MAR18.PDF
R339 = RESISTOR: RES 7.5K 1/16W 5% 0402; Chkd/date: MAZHAR/280108; Crtd /date: USMAN/280108; Custom_Duty: 15%; Customs_HS_Code: 85332119; Distributor_name: DIGIKEY; Distributor_part_number: 541-7.5KJCT-ND; Footprint Path: Y:\MIS_DATABASE\Library\ALTIUM_TOOL\PCB_FOOTPRINTS\Altium_Footprint_Lib.PcbLib; Height: 0.40MM; Library Path: Y:\MIS_DATABASE\Library\ALTIUM_TOOL\SCHEMATICS_PARTS\MS_DISCRETE_Library.schlib; Mfr_name: VISHAY; Mfr_part_number: CRCW04027K50JNED; Mistral Part No: 110009031092-R; Package: 0402; Part_type: RESISTORS\FIXED; Project: TELEMETRY ENCODER; RoHS: RoHS; Temperature: -55°C+155°C; Tolerance: 5%; Voltage: NA; Wattage: 1/16W; Weight: 0.65mg; Datasheet: Y:\MIS_DATABASE\DATASHEETS\RESISTORS\CRCW0603.PDF
U11 = SII9022ACNU_QFN72: IC HDMI TRANSMITTER QFN72; Chkd/date: MANIRAJA/270818; Crtd /date: MUDDU/310510; Custom_Duty: 15%; Customs_HS_Code: 85423100; Distributor_name: NA; Distributor_part_number: NA; Footprint Path: Y:\MIS_DATABASE\Library\ALTIUM_TOOL\PCB_FOOTPRINTS\Altium_Footprint_Lib.PcbLib; Height: 0.90MM; Library Path: Y:\MIS_DATABASE\Library\ALTIUM_TOOL\SCHEMATICS_PARTS\MS_COMBINATIONAL_Library.schlib; Library Ref: SiI9022ACNU_QFN72; Mfr_name: SILICON IMAGE; Mistral Part No: 141010060001; Package: QFN72; Part_type: ICS\DIGITAL\PERIPHERAL; Project: CENTAURUS; RoHS: NA; Temperature: -20°C+85°C; Tolerance: NA; Voltage: NA; Wattage: NA; Weight: NA; Datasheet: Y:\MIS_DATABASE\DATASHEETS\ICS\DIGITAL\PERIPHERAL\SiI9022.PDF
U50 = TPD12S016PW_TSSOP24: IC HDMI COMPANION CHIP WITH I2C LEVEL SHIFTING,12-CH ESD TSSOP24; Chkd/date: MANIRAJA/110917; Crtd /date: BAVISH/180811; Custom_Duty: 15%; Customs_HS_Code: 85423100; Distributor_name: DIGIKEY; Distributor_part_number: 296-29690-1-ND; Height: 1.20MM; Mfr_name: TEXAS INSTRUMENTS; Mistral Part No: 141011080021-R; Package: TSSOP24; Part_type: ICS\INTERFACE; Project: DM385EVM_BASE-BOARD; RoHS: RoHS; Temperature: -40°C+85°C; Tolerance: NA; Voltage: NA; Wattage: NA; Weight: 212mg; Datasheet: Y:\MIS_DATABASE\DATASHEETS\ICS\INTERFACE\TPD12S016.PDF

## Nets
AGND_AUD: C124.2 C126.2 C132.2 C133.2 C398.2 C399.2 C402.2 C403.2 FL11.1 J14.4 TP67.1(TP) U66.15(AVSS_ADC) U66.20(DRVSS.1) U66.21(DRVSS.2) U66.26(AVSS_DAC) U66.49(TPAD)
DGND: C194.2 C197.2 C198.2 C201.2 C202.2 C205.2 C206.2 C208.1 C212.2 C213.2 C214.2 C215.2 C217.2 C219.2 C220.2 C221.2 C222.2 C223.2 C227.2 C232.1 C382.2 C383.2 C385.2 C388.2 C389.2 C412.2 FL6.1 FL11.2 J5.2 J5.5 J5.8 J5.11 J5.17 R32.1 R47.2 R156.2 R157.2 R296.1 R300.1 R338.2 R339.2 R456.1 R469.1 U9.2(GND) U11.43(CGND) U11.55(RSVDL) U11.57(IOGND) U11.63(AGND) U11.70(VDDQ) U11.73(PAD) U47.3(GND) U50.6(GND1) U50.14(GND2) U50.19(GND3) U64.2(GND) U66.42(DVSS) U66.43(SELECT) U71.3(GND) ; also on sheet 1 2 3 4 13 14 15 16 17 18 19 20 21 22 23 24 25 26 27 28 29 30 31 32 33 34 35 36 37 38 39 42 43
VCC1V8_SYS: R434.2 ; also on sheet 4 16 19 20 22 25 34 37 39 42
VCC_1V8_AUD: C388.1 C389.1 R434.1 U66.36(DVDD.1)
VCC_3V3_AUD: C132.1 C133.1 C382.1 C383.1 C385.1 C398.1 C399.1 C402.1 C403.1 C412.1 R422.1 R425.1 R426.1 R451.2 R457.1 U64.4(VCC) U66.16(DRVDD.1) U66.17(DRVDD.2) U66.24(DRVDD.3) U66.25(AVDD_DAC) U66.44(IOVDD) U71.5(VCC)
VCC_3V3_SYS: C194.1 C202.1 C208.2 C232.2 FB1.2 R39.2 R301.2 R342.2 R457.2 U9.4(VCC) U47.5(VCC) U50.24(VCCA) ; also on sheet 1 4 15 16 19 20 21 23 24 26 27 29 30 31 32 33 34 36 37 38 39 42 43
VCC_5V0: C217.1 U50.11(VCC5V) ; also on sheet 13 14 33 35 38
VCC_5V0_HDMICONN: C212.1 J5.18 U50.13(5V_OUT)
VDD_1V2: C201.1 C227.1 FB2.2 FB3.2 ; also on sheet 4
AUD_RSTn: R469.2 U66.33(~{RESET}) U71.4(Y)
AUDIO_EXT_REFCLK1: R348.2 ; also on sheet 33
AUDIO_MSTRCLK: R430.1 U66.37(MCLK)
GPIO_AUD_RSTn: R451.1 R456.2 U71.1(A) ; also on sheet 39
GPIO_HDMI_RSTn: R300.2 R301.1 U47.1(A) ; also on sheet 39
HDMI_AUDD1: TP16.1(TP) U11.40(SD1)
HDMI_AUDD2: TP15.1(TP) U11.39(SD2)
HDMI_AUDD3: TP14.1(TP) U11.37(SD3)
HDMI_CEC: U11.71(CEC_A) U50.1(CEC_A)
HDMI_CEC_D: TP17.1(TP) U11.50(CEC_D)
HDMI_CLK+: J5.10 U11.59(TXC+) U50.16(CLK+)
HDMI_CLK-: J5.12 U11.58(TXC-) U50.15(CLK-)
HDMI_CONN_I2CSCL: J5.15 U50.8(SCL_B)
HDMI_CONN_I2CSDA: J5.16 U50.9(SDA_B)
HDMI_CONNCEC: J5.13 U50.7(CEC_B)
HDMI_EARTH: FL6.2 J5.20 J5.21 J5.22 J5.23
HDMI_EXTSWING: R339.1 U11.56(EXT_SWING)
HDMI_HPD: R338.1 U11.54(HPD) U50.4(HPD_A)
HDMI_I2C_SCL: R317.2 U11.49(DSCL) U50.2(SCL_A)
HDMI_I2C_SDA: R310.2 U11.48(DSDA) U50.3(SDA_A)
HDMI_INTn: R41.2 U11.52(INT) ; also on sheet 39
HDMI_MSTRCLK: R34.2 R348.1 U11.38(MCLK)
HDMI_PCLK: R329.2 U11.22(IDCK)
HDMI_RSTn: R296.2 U11.51(RESET#) U47.4(Y)
HDMI_TX0+: J5.7 U11.62(TX0+) U50.18(D0+)
HDMI_TX0-: J5.9 U11.61(TX0-) U50.17(D0-)
HDMI_TX1+: J5.4 U11.65(TX1+) U50.21(D1+)
HDMI_TX1-: J5.6 U11.64(TX1-) U50.20(D1-)
HDMI_TX2+: J5.1 U11.68(TX2+) U50.23(D2+)
HDMI_TX2-: J5.3 U11.67(TX2-) U50.22(D2-)
HDMICONN_HPD: J5.19 U50.10(HPD_B)
HPLOUT: C408.2 J14.2
HPLOUT_C: C408.1 U66.18(HPLOUT)
HPROUT: C409.2 J14.3
HPROUT_C: C409.1 U66.23(HPROUT)
LINE1L+: C392.1 TP62.1(TP)
LINE1L+_C: C392.2 U66.3(LINE1L+)
LINE1R+: C394.1 TP63.1(TP)
LINE1R+_C: C394.2 U66.5(LINE1R+)
MCASP1_ACLKX_AUD: TP60.1(TP) U66.38(BCLK) ; also on sheet 39
MCASP1_ACLKX_HDMI: U11.45(SCK) ; also on sheet 39
MCASP1_AFSX_AUD: TP57.1(TP) U66.39(WCLK) ; also on sheet 39
MCASP1_AFSX_HDMI: U11.44(WS) ; also on sheet 39
MCASP1_AXR0_AUD: TP61.1(TP) U66.40(DIN) ; also on sheet 39
MCASP1_AXR0_HDMI: U11.41(SD0) ; also on sheet 39
MCASP1_AXR2_AUD: R427.1 TP55.1(TP) ; also on sheet 39
MFP0: R156.1 R426.2 U66.45(MFP0)
MFP1: R157.1 R425.2 U66.46(MFP1)
MFP2: TP58.1(TP) U66.47(MFP2)
MFP3: TP59.1(TP) U66.48(MFP3)
MIC_IN: C404.1 J14.1 R458.1 U66.12(MICDET)
RESETSTATz: U47.2(B) U71.2(B) ; also on sheet 1 4 20 21 22 24 27 32 37 38 39 42
SOC_I2C1_SCL: R429.1 U11.1(CSCL) ; also on sheet 16 23 26 39 42
SOC_I2C1_SDA: R428.1 U11.2(CSDA) ; also on sheet 16 23 26 39 42
SoC_VOUT0_DATA0: U11.32(D0) U12.R21(VOUT0_DATA0)
SoC_VOUT0_DATA1: U11.31(D1) U12.P18(VOUT0_DATA1)
SoC_VOUT0_DATA2: U11.30(D2) U12.R18(VOUT0_DATA2)
SoC_VOUT0_DATA3: U11.29(D3) U12.R19(VOUT0_DATA3)
SoC_VOUT0_DATA4: U11.28(D4) U12.R20(VOUT0_DATA4)
SoC_VOUT0_DATA5: U11.27(D5) U12.T20(VOUT0_DATA5)
SoC_VOUT0_DATA6: U11.25(D6) U12.T21(VOUT0_DATA6)
SoC_VOUT0_DATA7: U11.24(D7) U12.T19(VOUT0_DATA7)
SoC_VOUT0_DATA8: U11.23(D8) U12.U21(VOUT0_DATA8)
SoC_VOUT0_DATA9: U11.20(D9) U12.R17(VOUT0_DATA9)
SoC_VOUT0_DATA10: U11.19(D10) U12.T18(VOUT0_DATA10)
SoC_VOUT0_DATA11: U11.18(D11) U12.U20(VOUT0_DATA11)
SoC_VOUT0_DATA12: U11.17(D12) U12.U19(VOUT0_DATA12)
SoC_VOUT0_DATA13: U11.16(D13) U12.V21(VOUT0_DATA13)
SoC_VOUT0_DATA14: U11.15(D14) U12.U18(VOUT0_DATA14)
SoC_VOUT0_DATA15: U11.14(D15) U12.V20(VOUT0_DATA15)
SoC_VOUT0_DATA16: U11.13(D16) ; also on sheet 32
SoC_VOUT0_DATA17: U11.11(D17) ; also on sheet 32
SoC_VOUT0_DATA18: U11.10(D18) ; also on sheet 32
SoC_VOUT0_DATA19: U11.9(D19) ; also on sheet 32
SoC_VOUT0_DATA20: U11.8(D20) ; also on sheet 32
SoC_VOUT0_DATA21: U11.7(D21) ; also on sheet 32
SoC_VOUT0_DATA22: U11.6(D22) ; also on sheet 32
SoC_VOUT0_DATA23: U11.4(D23) ; also on sheet 32
SoC_VOUT0_DE: U11.33(DE) U12.T17(VOUT0_DE)
SoC_VOUT0_HSYNC: U11.34(HSYNC) U12.W21(VOUT0_HSYNC)
SoC_VOUT0_PCLK: R329.1 U12.U17(VOUT0_PCLK)
SoC_VOUT0_VSYNC: U11.35(VSYNC) U12.T16(VOUT0_VSYNC)
VHDMI_AVCC_1V2: C220.1 C221.1 C223.1 FB3.1 U11.60(AVCC12_1) U11.66(AVCC12_2)
VHDMI_CVCC_1V2: C197.1 C205.1 C206.1 C214.1 C215.1 C219.1 FB2.1 U11.5(CVCC12_1) U11.12(CVCC12_2) U11.26(CVCC12_3) U11.42(CVCC12_4) U11.47(CVCC12_5) U11.53(CVCC12_6)
VHDMI_IOVCC_3V3: C198.1 C213.1 C222.1 FB1.1 R41.1 R48.1 R310.1 R317.1 U11.3(IOVCC1) U11.21(IOVCC2) U11.46(IOVCC3)
N16927060: R48.2 U11.72(CI2CA)
N16927228: R47.1 U11.69(IO_SEL)
N16927289: R32.2 U11.36(SPDIF)
N16929458: TP65.1(TP) U66.7(LINE2L+)
N16929460: TP64.1(TP) U66.8(LINE2L-)
N16929474: R427.2 U66.41(DOUT)
N16929699: C124.1 U66.4(LINE1L-)
N16929703: C126.1 U66.6(LINE1R-)
N16929744: TP69.1(TP) U66.19(HPLCOM)
N16929747: TP68.1(TP) U66.22(HPRCOM)
N16929749: TP102.1(TP) U66.35(GPIO1)
N16929751: TP103.1(TP) U66.34(GPIO2)
N17275147: R430.2 U64.3(OUTPUT)
N17285208: R342.1 U50.5(LS_OE) U50.12(CT_HPD)
N17498937: R428.2 U66.2(SDA)
N17498940: R429.2 U66.1(SCL)
N18736007: C404.2 U66.14(MIC3R)
N18736028: R458.2 U66.13(MICBIAS)
N18902581: R422.2 U64.1(INH)
N19081973: R39.1 U9.1(INH)
N19082749: R34.1 U9.3(OUTPUT)

Not connected (* = marked no-connect by the designer): J5 14*; U66 9(LINE2R+)* 10(LINE2R-)* 11(MIC3L)* 27(MONO_LO+)* 28(MONO_LO-)* 29(LEFT_LO+)* 30(LEFT_LO-)* 31(RIGHT_LO+)* 32(RIGHT_LO-)*

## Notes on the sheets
sheet 40
- AUDIO CODEC
- Silk: LINE IN
- MIC + HEADPHONE
- D-Note:-
  Add a bulk cap 1 uF
- I2C ADDRESS: 0x1B
- AUDIO CODEC RESET
- CODEC I2C ADDRESS SELECTION
- D-Note:-
  Add a series resistor to the GPIO
  input for isolation or testing
  Refer SK-AM62P-LP schematics
- MFP0
- MFP1
- Device Address
- 0
- 0
- 0x18
- 0
- 1
- 0x19
- 1
- 0
- 0x1A
- 1
- 1
- 0x1B
sheet 41
- HDMI INTERFACE
- R-Note :-
  Verify the implementation with
  the device manufacturer
- D-Note:-
  Add an additional decap
- D-Note:-
  Add bulk caps
- HDMI ESD DEVICE
- 100E
- Input Mode - RGB888
  Clock Mode - 1x
  Data Bus Width - 24
  (8 bits for Red and Blue and 8 bits for Green)
- 100E
- 100E
- 100E
- D-Note:-
  REXT_SWING modified to
  7.5K_5%. Value changed
  for internal testing
  (Radiated Emission)
  Refer device data sheet
  for the
  recommended value
- R-NOTE :-
  TPD12S016PWR has integrated pullup or pulldown resistors on the
  I2C and HPD lines hence no external pullup or pulldown required.
- D-Note:-
  Add a bulk cap 1uF
- HDMI CONNECTOR
- R-Note :-
  M_CLK is not used
- I2C ADDRESS: 0x3B, 0x3F, 0x62
- Silk: HDMI
- HDMI RESET
- D-Note:-
  Add a series resistor to the GPIO
  input for isolation or testing
  Refer SK-AM62P-LP schematics
